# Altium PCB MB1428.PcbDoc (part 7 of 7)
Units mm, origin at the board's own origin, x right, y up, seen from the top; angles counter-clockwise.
Board outline 55.88 x 152.4 mm, 4 copper layers (Top Layer, Signal Layer 1, Signal Layer 2, Bottom Layer), stack 1.614 mm thick; 396 components, 227 nets, 1346 pads, 1469 vias.
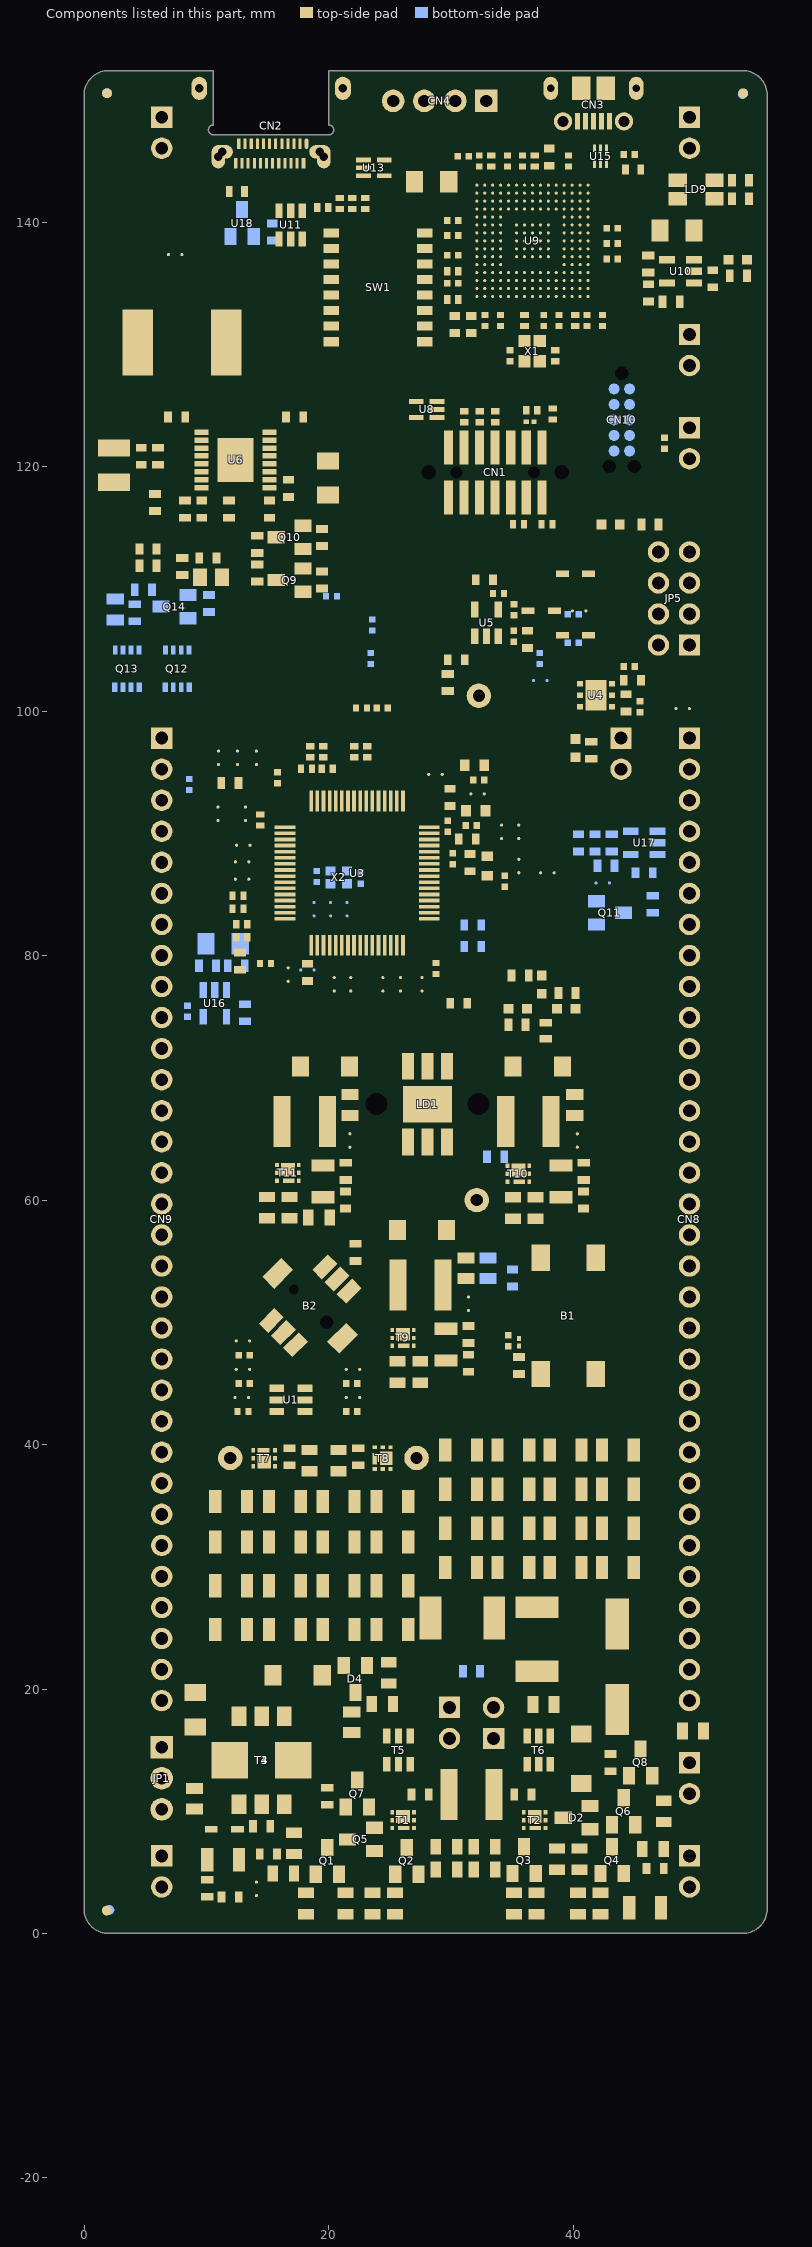
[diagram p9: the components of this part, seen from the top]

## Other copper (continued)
Signal Layer 2:
  text "3" at 6.895,140.09 h2.5
Bottom Layer:
  text "4" at 8.895,140.09 h2.5
Multi-Layer:
  pour cut-out: 1.395,142.34 1.395,139.34 9.895,139.34 9.895,142.34

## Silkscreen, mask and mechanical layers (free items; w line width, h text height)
Top Overlay:
  drawing of 466 lines, arcs and shapes, not listed
  text "3V3_STLK" at 31.8,151.4 h1.2
  text "USB / STLK" at 46.3,150.225 h1.2
  text "CN12" at 4.3,150.2 h1.5
  text "CN11" at 49.575,150.2 h1.5
  text "GND" at 51.325,148.15 h1.5
  text "GND" at 1.9,148.1 h1.5
  text "SWD" at 27.475,147.45 h1.5
  text "USB / TYPE-C" at 21.175,147.275 h1.2
  text "GND" at 51.325,145.675 h1.5
  text "GND" at 1.925,145.575 h1.5
  text "COM" at 51.75,138.85 h1.5
  text "PWREXT" at 10.65,138.675 h1.2
  text "VCCAIN" at 11.15,137.55 h1.2
  text "GNDDET" at 14.65,136.125 h1.2
  text "TVCP_RX" at 14.25,134.9 h1.2
  text "TVCP_TX" at 14.375,133.625 h1.2
  text "OC" at 52.275,132.525 h1.5
  text "TSWO" at 16.025,132.375 h1.2
  text "TSWCLK" at 14.75,131.075 h1.2
  text "TSWIO" at 15.775,129.85 h1.2
  text "TNRST" at 43.125,129.05 h1.5
  text "OFF" at 18.875,127.375 h1.5
  text "H" at 23.625,127.375 h1.5
  text "L" at 23.65,125.95 h1.5
  text "ON" at 19.475,125.775 h1.5
  text "CN10" at 42.35,123.325 h1.5
  text "GND" at 51.325,123 h1.5
  text "STLK" at 51.35,120.575 h1.5
  text "NRST" at 51.35,119.4 h1.5
  text "DEBUG" at 26.825,117.275 h1.5 r90
  text "STDC14" at 26.275,113.7 h1.5
  text "5V" at 43.675,112.825 h1.5
  text "CHGR" at 51.275,112.65 h1.5
  text "USBC" at 51.275,110.15 h1.5
  text "E5V" at 51.25,107.625 h1.5
  text "STLK" at 51.2,105 h1.5
  text "5V_SEL" at 50.375,102.45 h1.5
  text "E" at 1.05,101.65 h15
  text "J" at 11.25,100.775 h19
  text "RC Sinus" at 33.775,100.625 h1.5
  text "MB1428B" at 11.725,99.85 h2.5
  text "CN8" at 50.55,99.525 h1.5
  text "CN9" at 5.025,99.35 h1.5
  text "3V3" at 45.625,97.45 h1.2
  text "5V_I" at 1.75,97.375 h1.5
  text "3V3_O" at 51.3,97.35 h1.5
  text "3V3" at 36.925,96.45 h1.5
  text "GND" at 1.725,94.825 h1.5
  text "VDD" at 45.5,94.825 h1.2
  text "GND" at 51.25,94.725 h1.5
  text "5V_O" at 1.175,92.25 h1.5
  text "VDD" at 51.3,92.25 h1.5
  text "IDD" at 42.85,91.2 h1.5
  text "PA8" at 1.975,89.8 h1.5
  text "AGND" at 51.3,89.725 h1.5
  text "VREF" at 51.25,87.2 h1.5
  text "PA9" at 1.95,87.15 h1.5
  text "PA10" at 1.125,84.7 h1.5
  text "VREFP" at 51.15,84.6 h1.5
  text "AVDD" at 51.2,82.125 h1.5
  text "PA11" at 1.275,82.1 h1.5
  text "PA12" at 1.15,79.6 h1.5
  text "PC9" at 51.175,79.525 h1.5
  text "K" at 39.275,79 h14
  text "PC8" at 51.225,77.075 h1.5
  text "PA13" at 1.075,77 h1.5
  text "PC7" at 51.225,74.45 h1.5
  text "PA14" at 1.125,74.4 h1.5
  text "PC6" at 51.225,71.975 h1.5
  text "PA15" at 1.125,71.95 h1.5
  text "GREEN" at 40.625,70.5 h1.5
  text "BLUE" at 12.975,70.4 h1.5
  text "PB15" at 51.275,69.45 h1.5
  text "PC10" at 1.15,69.425 h1.5
  text "PB14" at 51.25,66.95 h1.5
  text "PC11" at 1.15,66.9 h1.5
  text "PB13" at 51.25,64.4 h1.5
  text "PC12" at 1.15,64.325 h1.5
  text "PB12" at 51.25,61.8 h1.5
  text "PD2" at 1.75,61.775 h1.5
  text "RGB LED" at 24.725,60.325 h1.5
  text "PB3" at 1.775,59.2 h1.5
  text "PB11" at 51.275,59.2 h1.5
  text "PB4" at 1.775,56.725 h1.5
  text "PB10" at 51.25,56.725 h1.5
  text "V_LED" at 30.525,56.325 h1.5
  text "PB2" at 51.25,54.275 h1.5
  text "JOYSTICK" at 8,54.25 h1.5
  text "PB5" at 1.825,54.175 h1.5
  text "PB1" at 51.275,51.75 h1.5
  text "PB6" at 1.9,51.575 h1.5
  text "PB0" at 51.25,49.175 h1.5
  text "PB7" at 1.9,49 h1.5
  text "PC5" at 51.25,46.6 h1.5
  text "PB8" at 1.925,46.475 h1.5
  text "PC4" at 51.25,44.075 h1.5
  text "PB9" at 1.95,43.975 h1.5
  text "RESET" at 37.625,42.8 h1.5
  text "RED" at 29.95,42.575 h1.5
  text "PA7" at 51.275,41.65 h1.5
  text "PC13" at 1.05,41.425 h1.5
  text "PA6" at 51.3,39.075 h1.5
  text "PC14" at 1.1,38.9 h1.5
  text "PC15" at 1.125,36.375 h1.5
  text "PA5" at 51.325,36.375 h1.5
  text "PA4" at 51.325,33.875 h1.5
  text "PF0" at 2.05,33.825 h1.5
  text "PA3" at 51.325,31.275 h1.5
  text "PF1" at 2.025,31.25 h1.5
  text "PA2" at 51.325,28.8 h1.5
  text "PC0" at 1.975,28.725 h1.5
  text "PA1" at 51.325,26.275 h1.5
  text "PC1" at 2.1,26.175 h1.5
  text "PA0" at 51.425,23.7 h1.5
  text "TNRST" at 0.275,23.6 h1.5
  text "PC2" at 1.95,21.125 h1.5
  text "PC3" at 51.4,21.125 h1.5
  text "GND" at 51.275,18.55 h1.5
  text "GND" at 1.65,18.525 h1.5
  text "USBPD" at 0.325,14.75 h1.5
  text "VOUT" at 51.5,13.5 h1.5
  text "VIN" at 2.125,12.25 h1.5
  text "GND" at 51.55,10.9 h1.5
  text "GND" at 1.675,9.625 h1.5
  text "CN7" at 51.225,8.525 h1.5
  text "GND" at 1.525,5.925 h1.5
  text "GND" at 51.3,5.925 h1.5
  text "GND" at 51.3,3.4 h1.5
  text "GND" at 1.675,3.35 h1.5
  text "CN5" at 50.225,1.275 h1.5
  text "CN6" at 5,1.2 h1.5
Bottom Overlay:
  drawing of 288 lines, arcs and shapes, not listed
  text "GND" at 4.475,148.25 h1.5
  text "GND" at 54.175,148.175 h1.5
  text "CN4" at 26.625,147.05 h1.5
  text "GND" at 54.125,145.6 h1.5
  text "CN3" at 42.825,145.575 h1.5
  text "GND" at 4.45,145.55 h1.5
  text "CN2" at 22.1,142.425 h1.5
  text "3V3_STLK" at 32.45,141.675 h1.5 r270
  text "JP7" at 50.8,132.425 h1.5
  text "TNRST" at 55.475,128.925 h1.5
  text "TAG" at 39.525,125.525 h1.5
  text "GND" at 54.175,122.725 h1.5
  text "STLK" at 54.45,120.725 h1.5
  text "NRST" at 54.625,119.45 h1.5
  text "JP6" at 50.8,117.875 h1.5
  text "CN1" at 30.575,115.125 h1.5
  text "CHGR" at 55.225,112.675 h1.5
  text "5V" at 45.1,112.65 h1.5
  text "USBC" at 54.9,110.05 h1.5
  text "E5V" at 54.325,107.4 h1.5
  text "STLK" at 54.75,104.875 h1.5
  text "Double / Switch" at 14.25,104.075 h1.5
  text "JP5" at 45.225,104.05 h1.5
  text "TP4" at 33.5,102.8 h1.5
  text "JP4" at 45.075,99.45 h1.5
  text "RC Sinus" at 35.025,98.65 h1.5
  text "5V_I" at 3.925,97.45 h1.5
  text "3V3" at 42.275,97.45 h1.5
  text "3V3_O" at 55.3,97.375 h1.5
  text "IDD" at 45.85,95.475 h1.5 r270
  text "GND" at 3.95,94.9 h1.5
  text "VDD" at 42.275,94.85 h1.5
  text "GND" at 55.35,94.75 h1.5
  text "5V_O" at 4.5,92.325 h1.5
  text "VDD" at 55.3,92.275 h1.5
  text "PA8" at 3.7,89.875 h1.5
  text "AGND" at 55.3,89.75 h1.5
  text "VREF PWR" at 38.55,88.725 h1.5
  text "PA9" at 3.725,87.225 h1.5
  text "VREF" at 55.35,87.225 h1.5
  text "PA10" at 4.55,84.775 h1.5
  text "VREFP" at 55.45,84.625 h1.5
  text "HSE CLK" at 29.35,83.8 h1.5
  text "PA11" at 4.4,82.175 h1.5
  text "AVDD" at 55.4,82.15 h1.5
  text "PA12" at 4.525,79.675 h1.5
  text "PC9" at 55.425,79.55 h1.5
  text "PC8" at 55.375,77.1 h1.5
  text "PA13" at 4.6,77.075 h1.5
  text "PA14" at 4.55,74.475 h1.5
  text "PC7" at 55.375,74.475 h1.5
  text "PA15" at 4.55,72.025 h1.5
  text "PC6" at 55.375,72 h1.5
  text "USB Detach" at 17.675,71.8 h1.5
  text "PC10" at 4.525,69.5 h1.5
  text "PB15" at 55.325,69.475 h1.5
  text "PC11" at 4.525,66.975 h1.5
  text "PB14" at 55.35,66.975 h1.5
  text "RGB LED" at 31.175,64.9 h1.5
  text "PB13" at 55.35,64.425 h1.5
  text "PC12" at 4.525,64.4 h1.5
  text "PD2" at 3.925,61.85 h1.5
  text "PB12" at 55.35,61.825 h1.5
  text "TP3" at 30.4,59.575 h1.5
  text "PB3" at 3.9,59.275 h1.5
  text "PB11" at 55.325,59.225 h1.5
  text "V_LED" at 34,57.475 h1.5
  text "PB4" at 3.9,56.8 h1.5
  text "PB10" at 55.35,56.75 h1.5
  text "PB2" at 55.35,54.3 h1.5
  text "PB5" at 3.85,54.25 h1.5
  text "PB1" at 55.325,51.775 h1.5
  text "PB6" at 3.775,51.65 h1.5
  text "PB0" at 55.35,49.2 h1.5
  text "PB7" at 3.775,49.075 h1.5
  text "C" at 41.65,46.7 h11
  text "PC5" at 55.35,46.625 h1.5
  text "PB8" at 3.75,46.55 h1.5
  text "I" at 28.65,45.25 h14
  text "PC4" at 55.35,44.1 h1.5
  text "PB9" at 3.725,44.05 h1.5
  text "PA7" at 55.325,41.675 h1.5
  text "PC13" at 4.625,41.5 h1.5
  text "PA6" at 55.3,39.1 h1.5
  text "PC14" at 4.575,38.975 h1.5
  text "TP1" at 15.925,38.525 h1.5
  text "TP2" at 31.325,38.375 h1.5
  text "H" at 44.675,36.85 h20
  text "PC15" at 4.55,36.45 h1.5
  text "PA5" at 55.275,36.4 h1.5
  text "PF0" at 3.625,33.9 h1.5
  text "PA4" at 55.275,33.9 h1.5
  text "PF1" at 3.65,31.325 h1.5
  text "PA3" at 55.275,31.3 h1.5
  text "PA2" at 55.275,28.825 h1.5
  text "PC0" at 3.7,28.8 h1.5
  text "PA1" at 55.275,26.3 h1.5
  text "PC1" at 3.575,26.25 h1.5
  text "PA0" at 55.175,23.725 h1.5
  text "TNRST" at 4.7,23.65 h1.5
  text "PC2" at 3.725,21.2 h1.5
  text "PC3" at 55.2,21.15 h1.5
  text "JP2" at 30.175,20.25 h1.5
  text "JP3" at 35.8,20.175 h1.5
  text "GND" at 4.025,18.6 h1.5
  text "GND" at 55.325,18.575 h1.5
  text "F" at 42.9,16.95 h11
  text "G" at 23.4,16.6 h12
  text "USBPD" at 4.65,14.875 h1.5
  text "IBB" at 28.075,14.825 h1.5
  text "IBB" at 37.4,14.825 h1.5
  text "VOUT" at 55,13.525 h1.5
  text "JP1" at 10.175,12.325 h1.5
  text "VIN" at 4.375,12.25 h1.5
  text "GND" at 54.05,10.875 h1.5
  text "GND" at 4.4,9.725 h1.5
  text "GND" at 4.55,5.9 h1.5
  text "GND" at 54.1,5.825 h1.5
  text "GND" at 4.575,3.375 h1.5
  text "GND" at 54.1,3.275 h1.5
Top Solder:
  rectangle: 1.645,139.59 9.645,142.09
Bottom Solder:
  rectangle: 1.645,139.59 9.645,142.09
M1-Board Shape:
  the board outline again, w0.1
M5-Top Constraints:
  lines w0.2: 64.139,8.469 266.95,8.469 ; 64.139,14.944 64.139,20.194 267.1,20.194 267.1,14.975 ; 64.139,26.654 267.1,26.654 ; 64.139,30.169 266.95,30.169 ; 64.139,36.644 64.139,41.894 267.1,41.894 267.1,36.675 ; 64.164,4.569 266.975,4.569 ; 64.714,39.344 85.675,39.344 ; 64.889,16.694 89.889,16.694 ; 84.639,1.125 84.639,14.969 ; 84.639,23.129 84.639,36.669 ; 105.139,1.125 105.139,14.969 ; 105.139,23.129 105.139,36.669 ; 125.639,1.125 125.639,14.969 ; 125.639,23.129 125.639,36.669 ; 146.139,1.125 146.139,14.969 ; 146.139,23.129 146.139,36.669 ; 171.4,1.15 171.4,14.969 146.139,14.969 ; 171.4,23.129 171.4,36.669 146.139,36.669 ; 196.65,1.1 196.65,14.969 171.389,14.969 ; 196.65,23.129 196.65,36.669 171.389,36.669 ; 221.925,14.969 196.664,14.969 ; 221.925,36.669 196.664,36.669 ; 221.939,1.125 221.939,14.969 238.939,14.969 ; 221.939,23.129 221.939,36.669 238.939,36.669 ; 238.939,1.1 238.939,14.969 ; 238.939,23.129 238.939,36.669 ; 255.939,1.075 255.939,14.969 ; 255.939,23.129 255.939,36.669 ; 84.639,14.969 105.139,14.969 ; 84.639,14.969 64.139,14.969 64.139,1.05 267.1,1.05 267.1,14.969 255.939,14.969 ; 84.639,36.669 105.139,36.669 ; 84.639,36.669 64.139,36.669 64.139,23.129 267.1,23.129 267.1,36.669 255.939,36.669 ; 105.139,14.969 105.139,14.969 ; 105.139,14.969 125.639,14.969 ; 105.139,36.669 105.139,36.669 ; 105.139,36.669 125.639,36.669 ; 125.639,14.969 146.139,14.969 ; 125.639,14.969 125.639,14.969 ; 125.639,36.669 146.139,36.669 ; 125.639,36.669 125.639,36.669 ; 146.139,14.969 146.139,14.969 ; 146.139,36.669 146.139,36.669 ; 171.389,14.969 171.389,14.969 ; 171.389,36.669 171.389,36.669 ; 196.664,14.969 196.664,14.969 ; 196.664,36.669 196.664,36.669 ; 238.939,14.969 255.939,14.969 ; 238.939,36.669 255.939,36.669
  text "IMPEDANCE TABLE    PIOxx & Others (MCO & NetR112_1 & NetR113_1 & NetR122_2 & NetSB23_2 & NetSB24_2 & PAxx & PBxx & PCxx & PDxx & PFxx & STLK_MCO & STLK_SWCLK &  /                                        STLK_SWDIO & STLK_VCP_RX & STLK_VCP_TX & T_NRST & T_SWCLK & T_SWCLKa & T_SWDIO & T_SWDIOa & T_SWOa & T_VCP_RX & T_VCP_TX)" at 64.7,36.925 h2.5
  text "IMPEDANCE" at 222.689,33.919 h3
  text "IMPEDANCE" at 239.689,33.919 h3
  text "LAYER" at 69.875,33.9 h3
  text "LAYER" at 90.375,33.9 h3
  text "TRACE" at 110.875,33.9 h3
  text "TOL." at 258.439,33.886 h3
  text "NET" at 133.025,33.775 h3
  text "SPACING" at 152.525,33.775 h3
  text "SPACING" at 177.775,33.775 h3
  text "SPACING" at 203.05,33.775 h3
  text "(Single ended)" at 223.189,31.169 h2.5
  text "(Differential)" at 240.939,31.169 h2.5
  text "\"GND mm\"" at 202.525,30.925 h3
  text "\"Ref GND\"" at 88.225,30.875 h3
  text "\"Width mm\"" at 108.725,30.875 h3
  text "\"Others Net mm\"" at 174.1,30.85 h3
  text "\"Routing\"" at 68.45,30.775 h3
  text "\"Intra Diff. Pair mm\"" at 147.125,30.775 h3
  text "\"Lenght mm\"" at 128.1,30.6 h3
  text "L2 (Sig_Lay1)" at 86.45,27.625 h3
  text "L1 (Top_Lay)" at 66.5,27.575 h3
  text "0.212 Min." at 177.9,27.475 h3
  text "0.120" at 111.6,27.45 h3
  text "n/a" at 156.7,27.425 h3
  text "Minimum" at 130.6,27.4 h3
  text "n/a" at 245.6,27.4 h3
  text "+/- 10%" at 256.875,27.4 h3
  text "55 Ohms" at 224.55,27.375 h3
  text "0.212 Min." at 202.95,27.325 h3
  text "L3 (Sig_Lay2)" at 86.45,24.1 h3
  text "L4 (Bot_Lay)" at 66.5,24.05 h3
  text "0.212 Min." at 177.9,23.95 h3
  text "0.120" at 111.6,23.925 h3
  text "n/a" at 156.7,23.9 h3
  text "Minimum" at 130.6,23.875 h3
  text "n/a" at 245.6,23.875 h3
  text "+/- 10%" at 256.875,23.875 h3
  text "55 Ohms" at 224.55,23.85 h3
  text "0.212 Min." at 202.95,23.8 h3
  text "IMPEDANCE TABLE    USB  (D & USBPDFS_D & USB_DEV_HS_CN & USB_DEV_HS )" at 64.889,17.194 h3
  text "LAYER" at 69.875,12.2 h3
  text "LAYER" at 90.375,12.2 h3
  text "TRACE" at 110.875,12.2 h3
  text "IMPEDANCE" at 222.689,12.219 h3
  text "IMPEDANCE" at 239.689,12.219 h3
  text "TOL." at 258.439,12.186 h3
  text "NET" at 133.025,12.075 h3
  text "SPACING" at 152.525,12.075 h3
  text "SPACING" at 177.775,12.075 h3
  text "SPACING" at 203.05,12.075 h3
  text "(Single ended)" at 223.189,9.469 h2.5
  text "(Differential)" at 240.939,9.469 h2.5
  text "\"GND mm\"" at 202.525,9.225 h3
  text "\"Ref GND\"" at 88.225,9.175 h3
  text "\"Width mm\"" at 108.725,9.175 h3
  text "\"Others Net mm\"" at 174.1,9.15 h3
  text "\"Routing\"" at 68.45,9.075 h3
  text "\"Intra Diff. Pair mm\"" at 147.125,9.075 h3
  text "\"Lenght mm\"" at 128.1,8.9 h3
  text "L1 (Top_Lay)" at 66.675,5.65 h3
  text "L2 (Sig_Lay1)" at 86.5,5.6 h3
  text "0.160" at 111.475,5.575 h3
  text "90 Ohms" at 242.15,5.5 h3
  text "+/- 10%" at 256.969,5.504 h3
  text "0.226 Min." at 177.875,5.45 h3
  text "0.452 Min." at 203.425,5.425 h3
  text "n/a" at 228.575,5.375 h3
  text "Minimum" at 131.2,5.35 h3
  text "0.226" at 155.775,5.35 h3
  text "L4 (Bot_Lay)" at 66.625,2 h3
  text "L3 (Sig_Lay2)" at 86.475,1.9 h3
  text "+/- 10%" at 256.969,1.854 h3
  text "0.160" at 111.475,1.825 h3
  text "90 Ohms" at 242.2,1.825 h3
  text "0.226 Min." at 177.875,1.8 h3
  text "0.452 Min." at 203.425,1.775 h3
  text "n/a" at 228.575,1.725 h3
  text "Minimum" at 131.2,1.7 h3
  text "0.226" at 155.775,1.7 h3
Drill Drawing:
  drawing of 458 lines, arcs and shapes, not listed
  text "THE COMPONENTS WITH PLATED THROUGH HOLE (PTH) MAY BE WELDED (CABLED) IN \"PIN-IN-PASTE\" MODE (IF NECESSARY)" at -22.375,202.475 h5
  text "PCB SPECIFICATIONS :" at -15.405,197.305 h3
  text "PCB : TYPE 3" at 132.351,196.903 h3
  text "A.   MATERIAL :" at -15.405,193.305 h3
  text "FR-4" at 23.095,193.305 h3
  text "X  TG-170" at 39.595,193.305 h3
  text "TG-150" at 57.845,193.305 h3
  text "TG-140" at 73.845,193.305 h3
  text "ASPECT-RATIO, AXE Z :" at 132.351,191.403 h3
  text "B.   MATERIAL FAMILY :" at -15.405,190.305 h3
  text "N/A" at 23.095,190.305 h3
  text "C.   SOLDERMASK COLOR :" at -15.405,187.305 h3
  text "GREEN" at 23.095,187.305 h3
  text "WHITE" at 39.595,187.305 h3
  text "RED" at 57.845,187.305 h3
  text "X  BLUE" at 73.845,187.305 h3
  text "6:1 to 8:1 / LEVEL \"B\"" at 132.37,184.655 h3
  text "D.   SILKSCREEN COLOR :" at -15.405,184.305 h3
  text "X  WHITE" at 23.095,184.305 h3
  text "YELLOW" at 39.595,184.305 h3
  text "BLACK" at 57.845,184.305 h3
  text "Blue ink PANTONE 2955" at 73.845,184.305 h3
  text "E.   SURFACE FINISH :" at -15.405,181.305 h3
  text "X  ENIG" at 23.095,181.305 h3
  text "IMMERSION SILVER" at 39.595,181.305 h3
  text "IMMERSION TIN" at 73.845,181.305 h3
  text "HASL" at 23.095,178.305 h3
  text "HASL (PB-FREE)" at 39.595,178.305 h3
  text "GOLDEN FINGER" at 73.845,178.305 h3
  text "MINIMUM PARAMETERS" at 132.37,177.555 h3
  text "F.   IMPEDANCE CONTROL :" at -15.405,175.305 h3
  text "NO" at 23.095,175.305 h3
  text "X  YES  (SEE IMPEDANCE TABLE FOR DETAIL INFORMATION)" at 39.595,175.305 h3
  text "G.   THROUGH VIA :" at -15.405,172.305 h3
  text "PLUG THE VIAS WHICH ARE COVERED WITH SOLDERMASK ONE OR TWO SIDE." at 23.095,172.305 h3
  text "DEFAULT" at 132.37,172.055 h3
  text "PLUG MATERIAL :" at 23.095,169.305 h3
  text "X  SOLDERMASK" at 48.595,169.305 h3
  text "NON-CONDUCTIVE EPOXY." at 73.845,169.305 h3
  text "H.   STACK-UP :" at -15.405,166.305 h3
  text "SEE LAYER STACK-UP SEQUENCE FOR OVERALL THICKNESS." at 23.095,166.305 h3
  text "TRACKS : 0.120mm           / GAPS : 0.120mm" at 132.37,166.305 h3
  text "Layer" at 67.268,142.4 h2.5
  text "Name" at 77.733,142.4 h2.5
  text "Material" at 97.975,142.4 h2.5
  text "Thickness" at 116.164,142.4 h2.5
  text "Constant" at 131.105,142.4 h2.5
  text "Board Layer Stack" at 144.933,142.4 h2.5
  text "1" at 67.268,137.4 h2.5
  text "Top Overlay" at 77.733,137.4 h2.5
  text "2" at 67.268,132.4 h2.5
  text "Top Solder" at 77.733,132.4 h2.5
  text "Solder Resist" at 97.975,132.4 h2.5
  text "0,015mm" at 116.164,132.4 h2.5
  text "3,5" at 131.105,132.4 h2.5
  text "3" at 67.268,127.4 h2.5
  text "Top Layer" at 77.733,127.4 h2.5
  text "Copper" at 97.975,127.4 h2.5
  text "0,042mm" at 116.164,127.4 h2.5
  text "4" at 67.268,122.4 h2.5
  text "Dielectric 1" at 77.733,122.4 h2.5
  text "PP-IT-180A" at 97.975,122.4 h2.5
  text "0,106mm" at 116.164,122.4 h2.5
  text "4,2" at 131.105,122.4 h2.5
  text "5" at 67.268,117.4 h2.5
  text "Signal Layer 1" at 77.733,117.4 h2.5
  text "Copper" at 97.975,117.4 h2.5
  text "0,035mm" at 116.164,117.4 h2.5
  text "6" at 67.268,112.4 h2.5
  text "Dielectric 2" at 77.733,112.4 h2.5
  text "FR4" at 97.975,112.4 h2.5
  text "1,248mm" at 116.164,112.4 h2.5
  text "4,2" at 131.105,112.4 h2.5
  text "7" at 67.268,107.4 h2.5
  text "Signal Layer 2" at 77.733,107.4 h2.5
  text "Copper" at 97.975,107.4 h2.5
  text "0,035mm" at 116.164,107.4 h2.5
  text "8" at 67.268,102.4 h2.5
  text "Dielectric 3" at 77.733,102.4 h2.5
  text "PP-IT-180A" at 97.975,102.4 h2.5
  text "0,106mm" at 116.164,102.4 h2.5
  text "4,2" at 131.105,102.4 h2.5
  text "9" at 67.268,97.4 h2.5
  text "Bottom Layer" at 77.733,97.4 h2.5
  text "Copper" at 97.975,97.4 h2.5
  text "0,042mm" at 116.164,97.4 h2.5
  text "10" at 67.268,92.4 h2.5
  text "Bottom Solder" at 77.733,92.4 h2.5
  text "Solder Resist" at 97.975,92.4 h2.5
  text "0,015mm" at 116.164,92.4 h2.5
  text "3,5" at 131.105,92.4 h2.5
  text "11" at 67.268,87.4 h2.5
  text "Bottom Overlay" at 77.733,87.4 h2.5
  text "Symbol" at 67.163,76.315 h3
  text "Count" at 78.915,76.315 h3
  text "Hole Size" at 92.2,76.315 h3
  text "Plated" at 115.04,76.315 h3
  text "Hole Type" at 125.356,76.315 h3
  text "Drill Layer Pair" at 140.375,76.315 h3
  text "Via/Pad" at 168.843,76.315 h3
  text "Hole Length" at 181.149,76.315 h3
  text "Routed Path Length" at 205.232,76.315 h3
  text "1469" at 78.915,71.137 h2.5
  text "0,200mm (7,87mil)" at 92.2,71.137 h2.5
  text "PTH" at 115.04,71.137 h2.5
  text "Round" at 125.356,71.137 h2.5
  text "Top Layer - Bottom Layer" at 140.375,71.137 h2.5
  text "Via" at 168.843,71.137 h2.5
  text "-" at 181.149,71.137 h2.5
  text "-" at 205.232,71.137 h2.5
  text "2" at 78.915,65.96 h2.5
  text "0,600mm (23,62mil)" at 92.2,65.96 h2.5
  text "PTH" at 115.04,65.96 h2.5
  text "Slot" at 125.356,65.96 h2.5
  text "Top Layer - Bottom Layer" at 140.375,65.96 h2.5
  text "Pad" at 168.843,65.96 h2.5
  text "1,300mm (51,18mil)" at 181.149,65.96 h2.5
  text "0,700mm (27,56mil)" at 205.232,65.96 h2.5
  text "2" at 78.915,60.782 h2.5
  text "0,700mm (27,56mil)" at 92.2,60.782 h2.5
  text "PTH" at 115.04,60.782 h2.5
  text "Slot" at 125.356,60.782 h2.5
  text "Top Layer - Bottom Layer" at 140.375,60.782 h2.5
  text "Pad" at 168.843,60.782 h2.5
  text "1,300mm (51,18mil)" at 181.149,60.782 h2.5
  text "0,600mm (23,62mil)" at 205.232,60.782 h2.5
  text "2" at 78.915,55.605 h2.5
  text "0,700mm (27,56mil)" at 92.2,55.605 h2.5
  text "PTH" at 115.04,55.605 h2.5
  text "Slot" at 125.356,55.605 h2.5
  text "Top Layer - Bottom Layer" at 140.375,55.605 h2.5
  text "Pad" at 168.843,55.605 h2.5
  text "1,350mm (53,15mil)" at 181.149,55.605 h2.5
  text "0,650mm (25,59mil)" at 205.232,55.605 h2.5
  text "2" at 78.915,50.427 h2.5
  text "0,700mm (27,56mil)" at 92.2,50.427 h2.5
  text "PTH" at 115.04,50.427 h2.5
  text "Slot" at 125.356,50.427 h2.5
  text "Top Layer - Bottom Layer" at 140.375,50.427 h2.5
  text "Pad" at 168.843,50.427 h2.5
  text "1,500mm (59,06mil)" at 181.149,50.427 h2.5
  text "0,800mm (31,50mil)" at 205.232,50.427 h2.5
  text "1" at 78.915,45.25 h2.5
  text "0,800mm (31,50mil)" at 92.2,45.25 h2.5
  text "NPTH" at 115.04,45.25 h2.5
  text "Round" at 125.356,45.25 h2.5
  text "Top Layer - Bottom Layer" at 140.375,45.25 h2.5
  text "Pad" at 168.843,45.25 h2.5
  text "-" at 181.149,45.25 h2.5
  text "-" at 205.232,45.25 h2.5
  text "2" at 78.915,40.073 h2.5
  text "0,900mm (35,43mil)" at 92.2,40.073 h2.5
  text "PTH" at 115.04,40.073 h2.5
  text "Round" at 125.356,40.073 h2.5
  text "Top Layer - Bottom Layer" at 140.375,40.073 h2.5
  text "Pad" at 168.843,40.073 h2.5
  text "-" at 181.149,40.073 h2.5
  text "-" at 205.232,40.073 h2.5
  text "2" at 78.915,34.895 h2.5
  text "0,970mm (38,19mil)" at 92.2,34.895 h2.5
  text "NPTH" at 115.04,34.895 h2.5
  text "Round" at 125.356,34.895 h2.5
  text "Top Layer - Bottom Layer" at 140.375,34.895 h2.5
  text "Pad" at 168.843,34.895 h2.5
  text "-" at 181.149,34.895 h2.5
  text "-" at 205.232,34.895 h2.5
  text "11" at 78.915,29.718 h2.5
  text "1,000mm (39,37mil)" at 92.2,29.718 h2.5
  text "PTH" at 115.04,29.718 h2.5
  text "Round" at 125.356,29.718 h2.5
  text "Top Layer - Bottom Layer" at 140.375,29.718 h2.5
  text "Pad" at 168.843,29.718 h2.5
  text "-" at 181.149,29.718 h2.5
  text "-" at 205.232,29.718 h2.5
  text "92" at 78.915,24.54 h2.5
  text "1,050mm (41,34mil)" at 92.2,24.54 h2.5
  text "PTH" at 115.04,24.54 h2.5
  text "Round" at 125.356,24.54 h2.5
  text "Top Layer - Bottom Layer" at 140.375,24.54 h2.5
  text "Pad" at 168.843,24.54 h2.5
  text "-" at 181.149,24.54 h2.5
  text "-" at 205.232,24.54 h2.5
  text "4" at 78.915,19.363 h2.5
  text "1,100mm (43,31mil)" at 92.2,19.363 h2.5
  text "NPTH" at 115.04,19.363 h2.5
  text "Round" at 125.356,19.363 h2.5
  text "Top Layer - Bottom Layer" at 140.375,19.363 h2.5
  text "Pad" at 168.843,19.363 h2.5
  text "-" at 181.149,19.363 h2.5
  text "-" at 205.232,19.363 h2.5
  text "2" at 78.915,14.185 h2.5
  text "1,190mm (46,85mil)" at 92.2,14.185 h2.5
  text "NPTH" at 115.04,14.185 h2.5
  text "Round" at 125.356,14.185 h2.5
  text "Top Layer - Bottom Layer" at 140.375,14.185 h2.5
  text "Pad" at 168.843,14.185 h2.5
  text "-" at 181.149,14.185 h2.5
  text "-" at 205.232,14.185 h2.5
  text "2" at 78.915,9.008 h2.5
  text "1,800mm (70,87mil)" at 92.2,9.008 h2.5
  text "NPTH" at 115.04,9.008 h2.5
  text "Slot" at 125.356,9.008 h2.5
  text "Top Layer - Bottom Layer" at 140.375,9.008 h2.5
  text "Pad" at 168.843,9.008 h2.5
  text "3,800mm (149,61mil)" at 181.149,9.008 h2.5
  text "2,000mm (78,74mil)" at 205.232,9.008 h2.5
  text "1593 Total" at 78.915,3.831 h2.5
  text "Slot definitions :" at 67.163,0.206 h2.5
  text "Routed Path Length" at 84.224,0.206 h2.5
  text "= Calculated from tool start centre position to tool end centre position." at 105.36,0.206 h2.5
  text "Hole Length" at 84.224,-1.865 h2.5
  text "= Routed Path Length + Tool Size = Slot length as defined in the PCB layout" at 97.514,-1.865 h2.5

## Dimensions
0,150.4 to 55.88,150.4 on M2-Board Dimensions
20.025,152.4 to 2,0 on M2-Board Dimensions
